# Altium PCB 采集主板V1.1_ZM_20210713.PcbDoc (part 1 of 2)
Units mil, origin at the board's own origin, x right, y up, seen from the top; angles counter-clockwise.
Board outline 5118.11 x 2559.06 mil, 4 copper layers (Top Layer, GND, Power, Bottom Layer), stack 30.635 mil thick; 191 components, 119 nets, 558 pads, 477 vias.
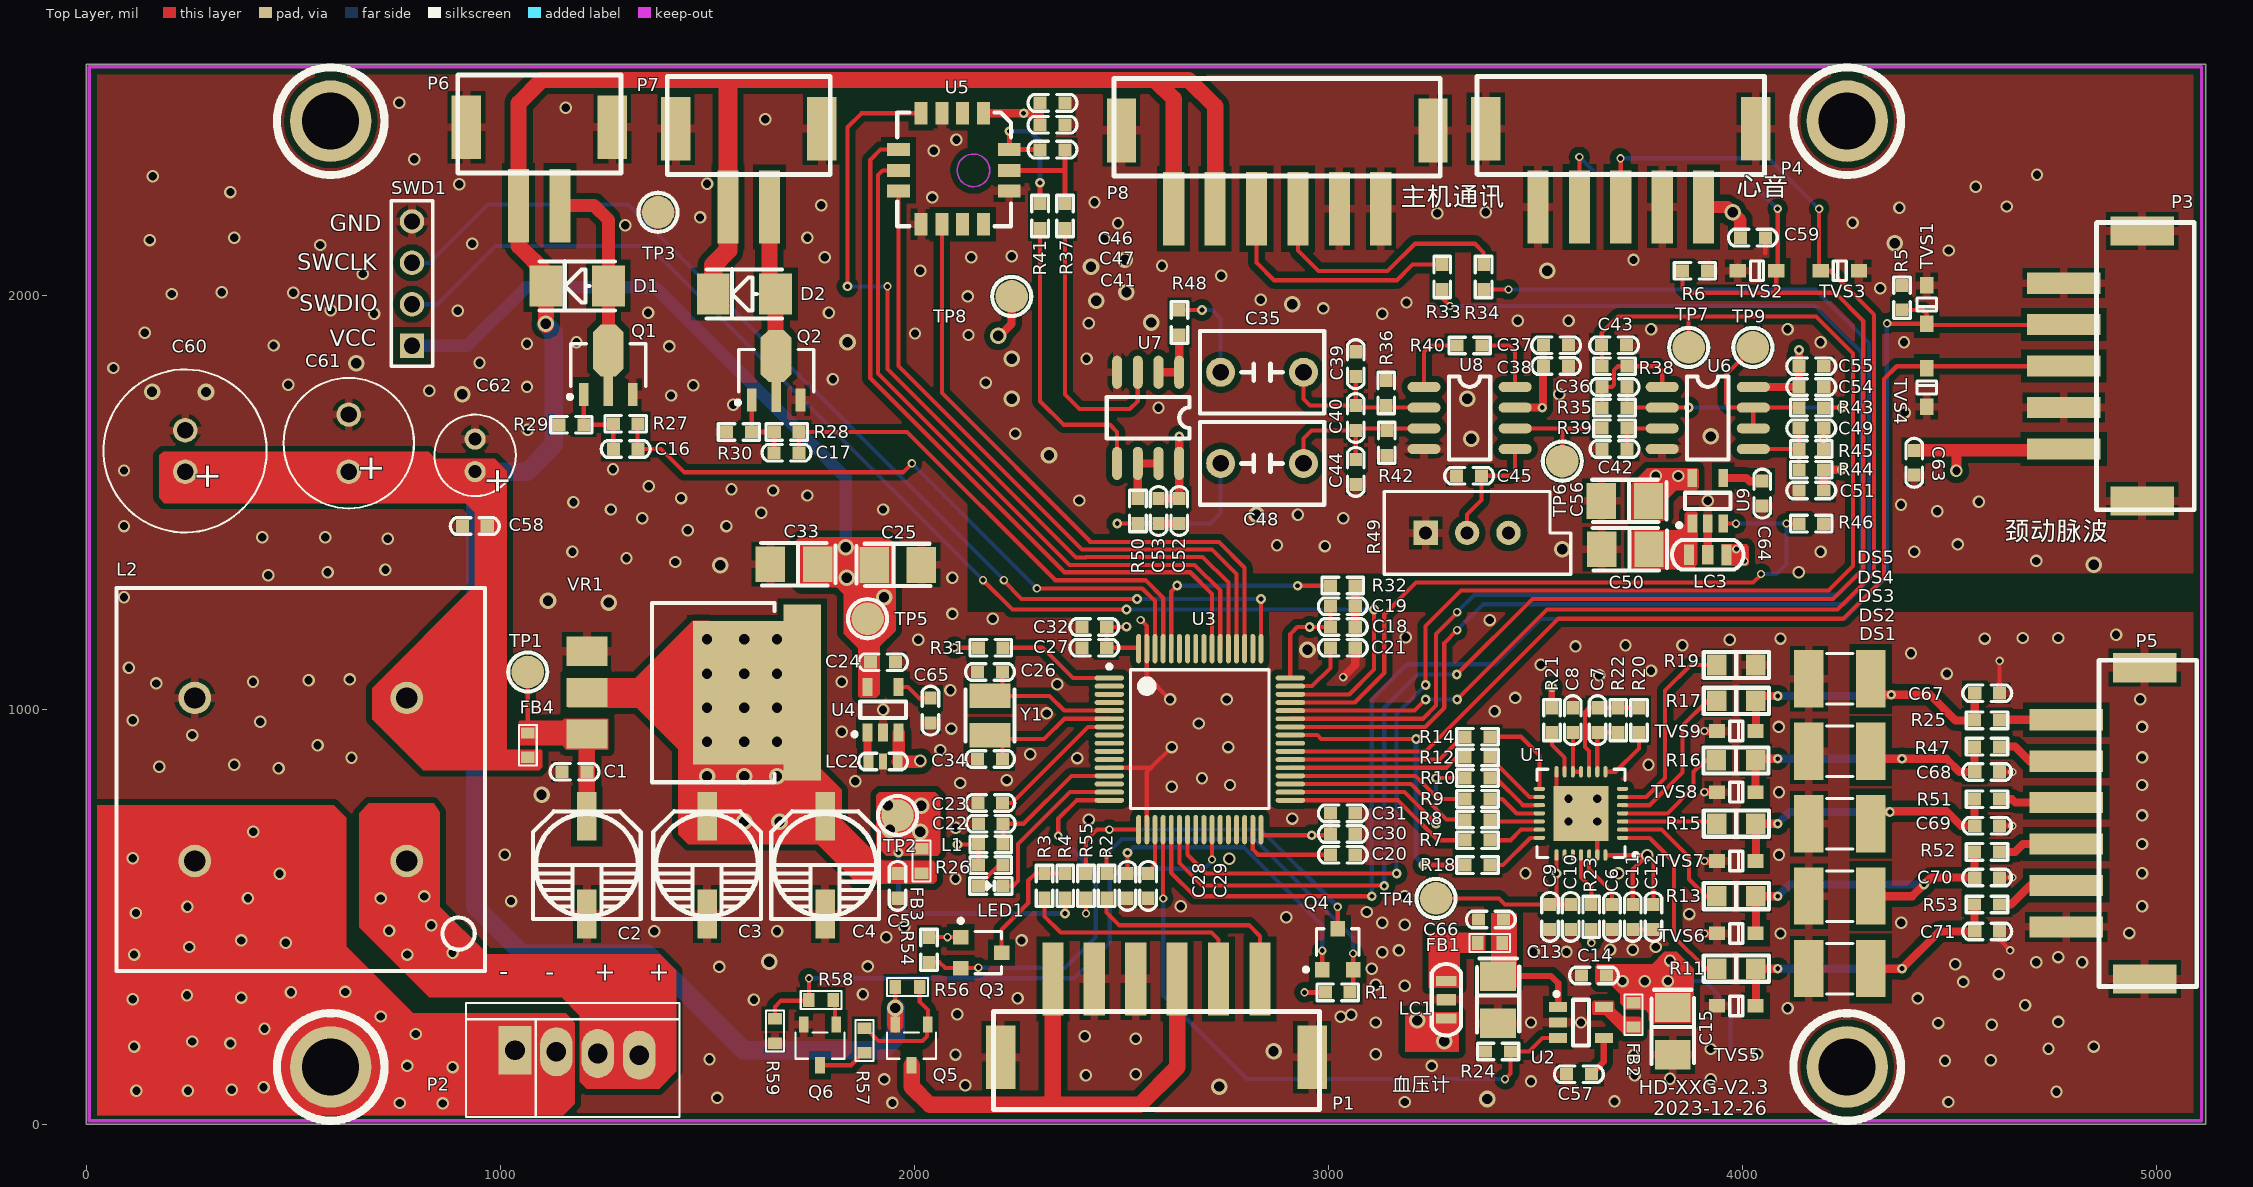
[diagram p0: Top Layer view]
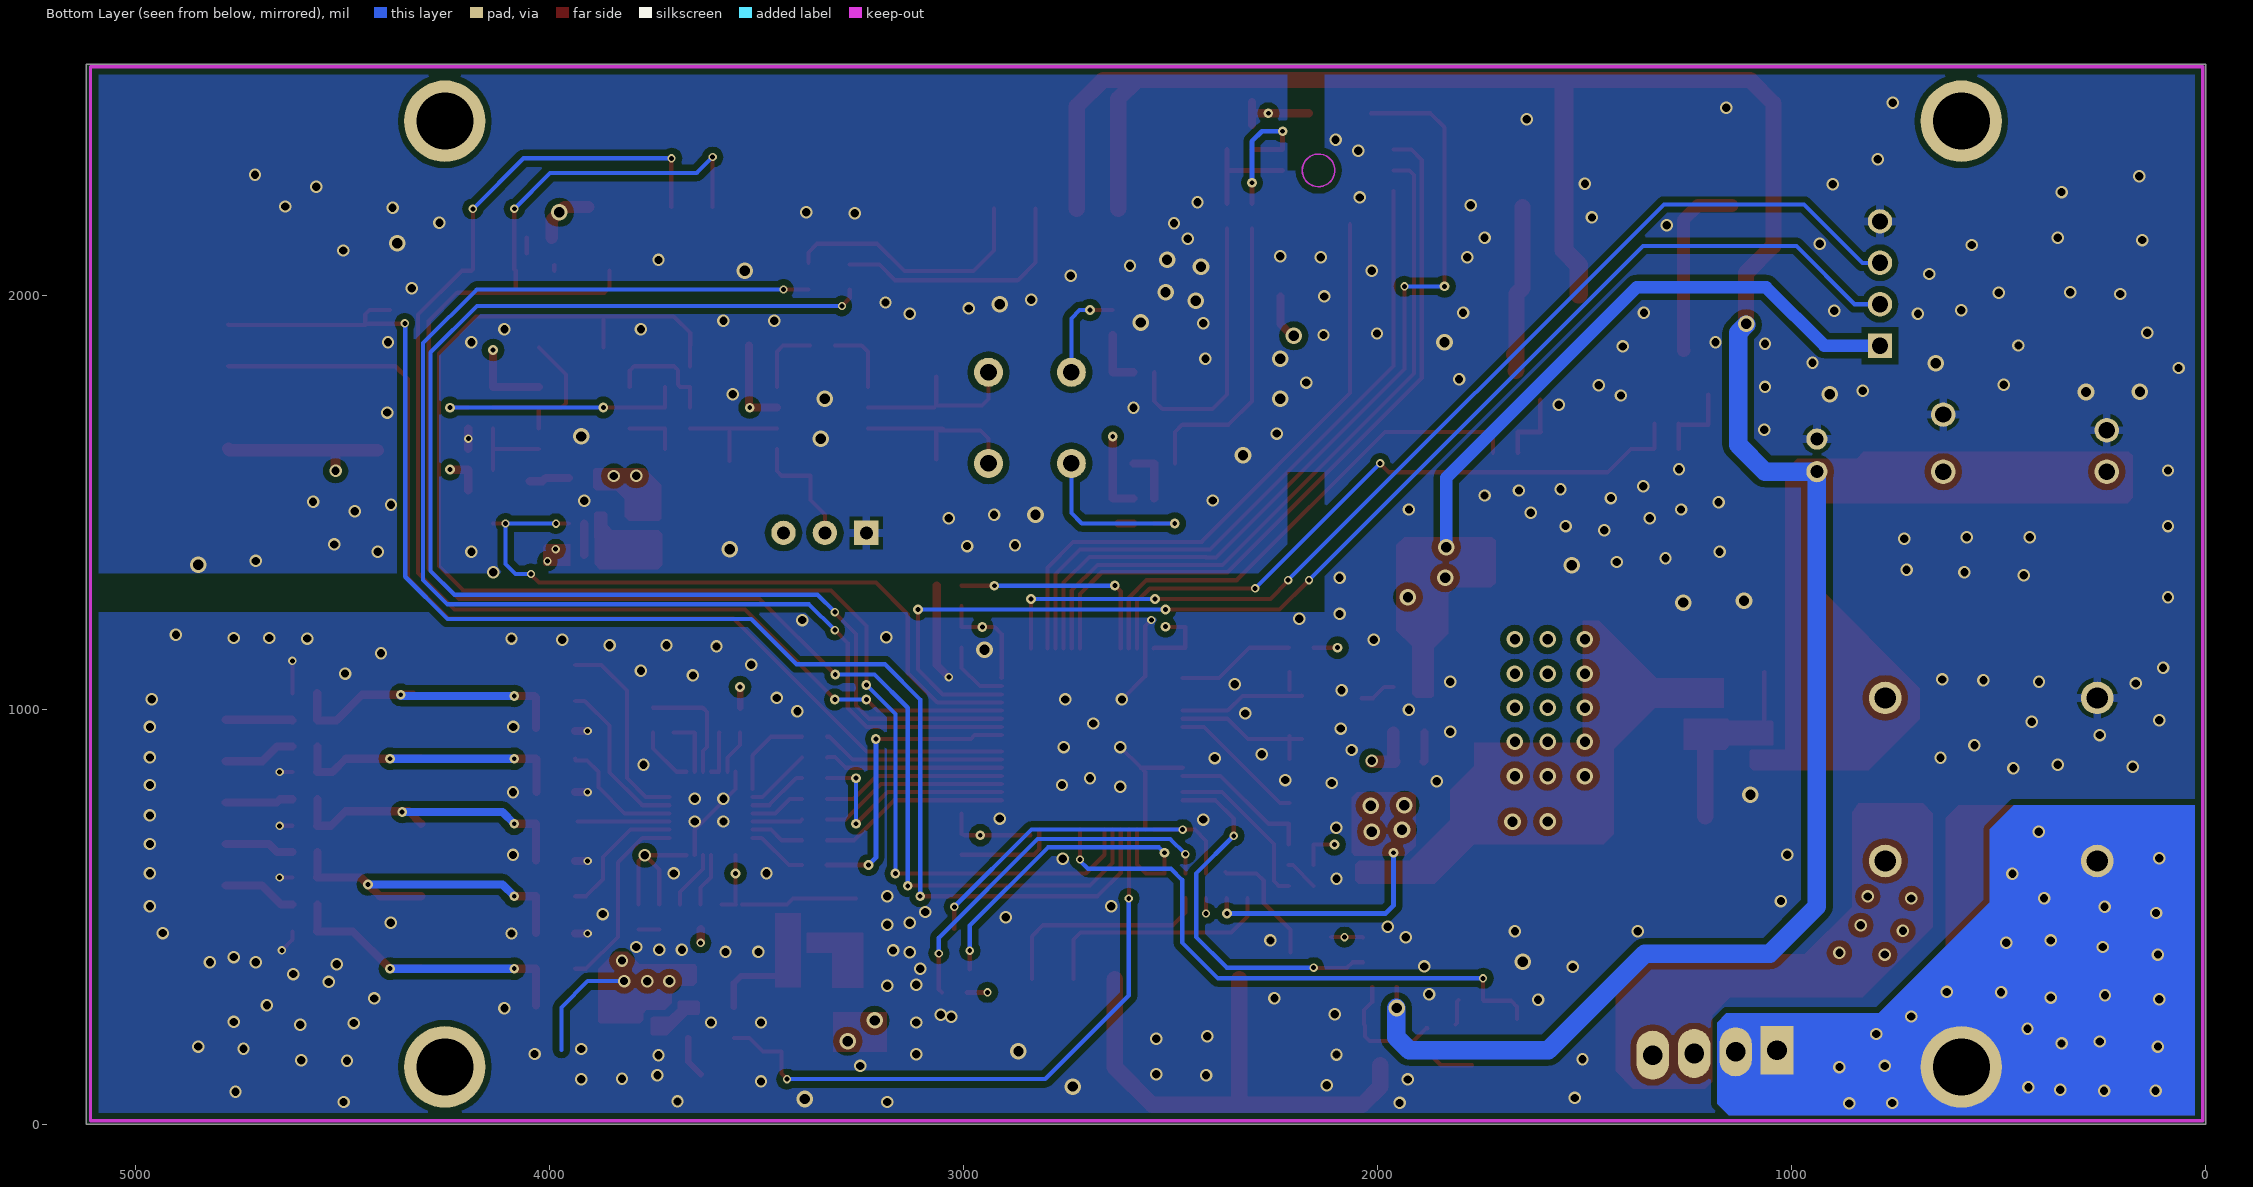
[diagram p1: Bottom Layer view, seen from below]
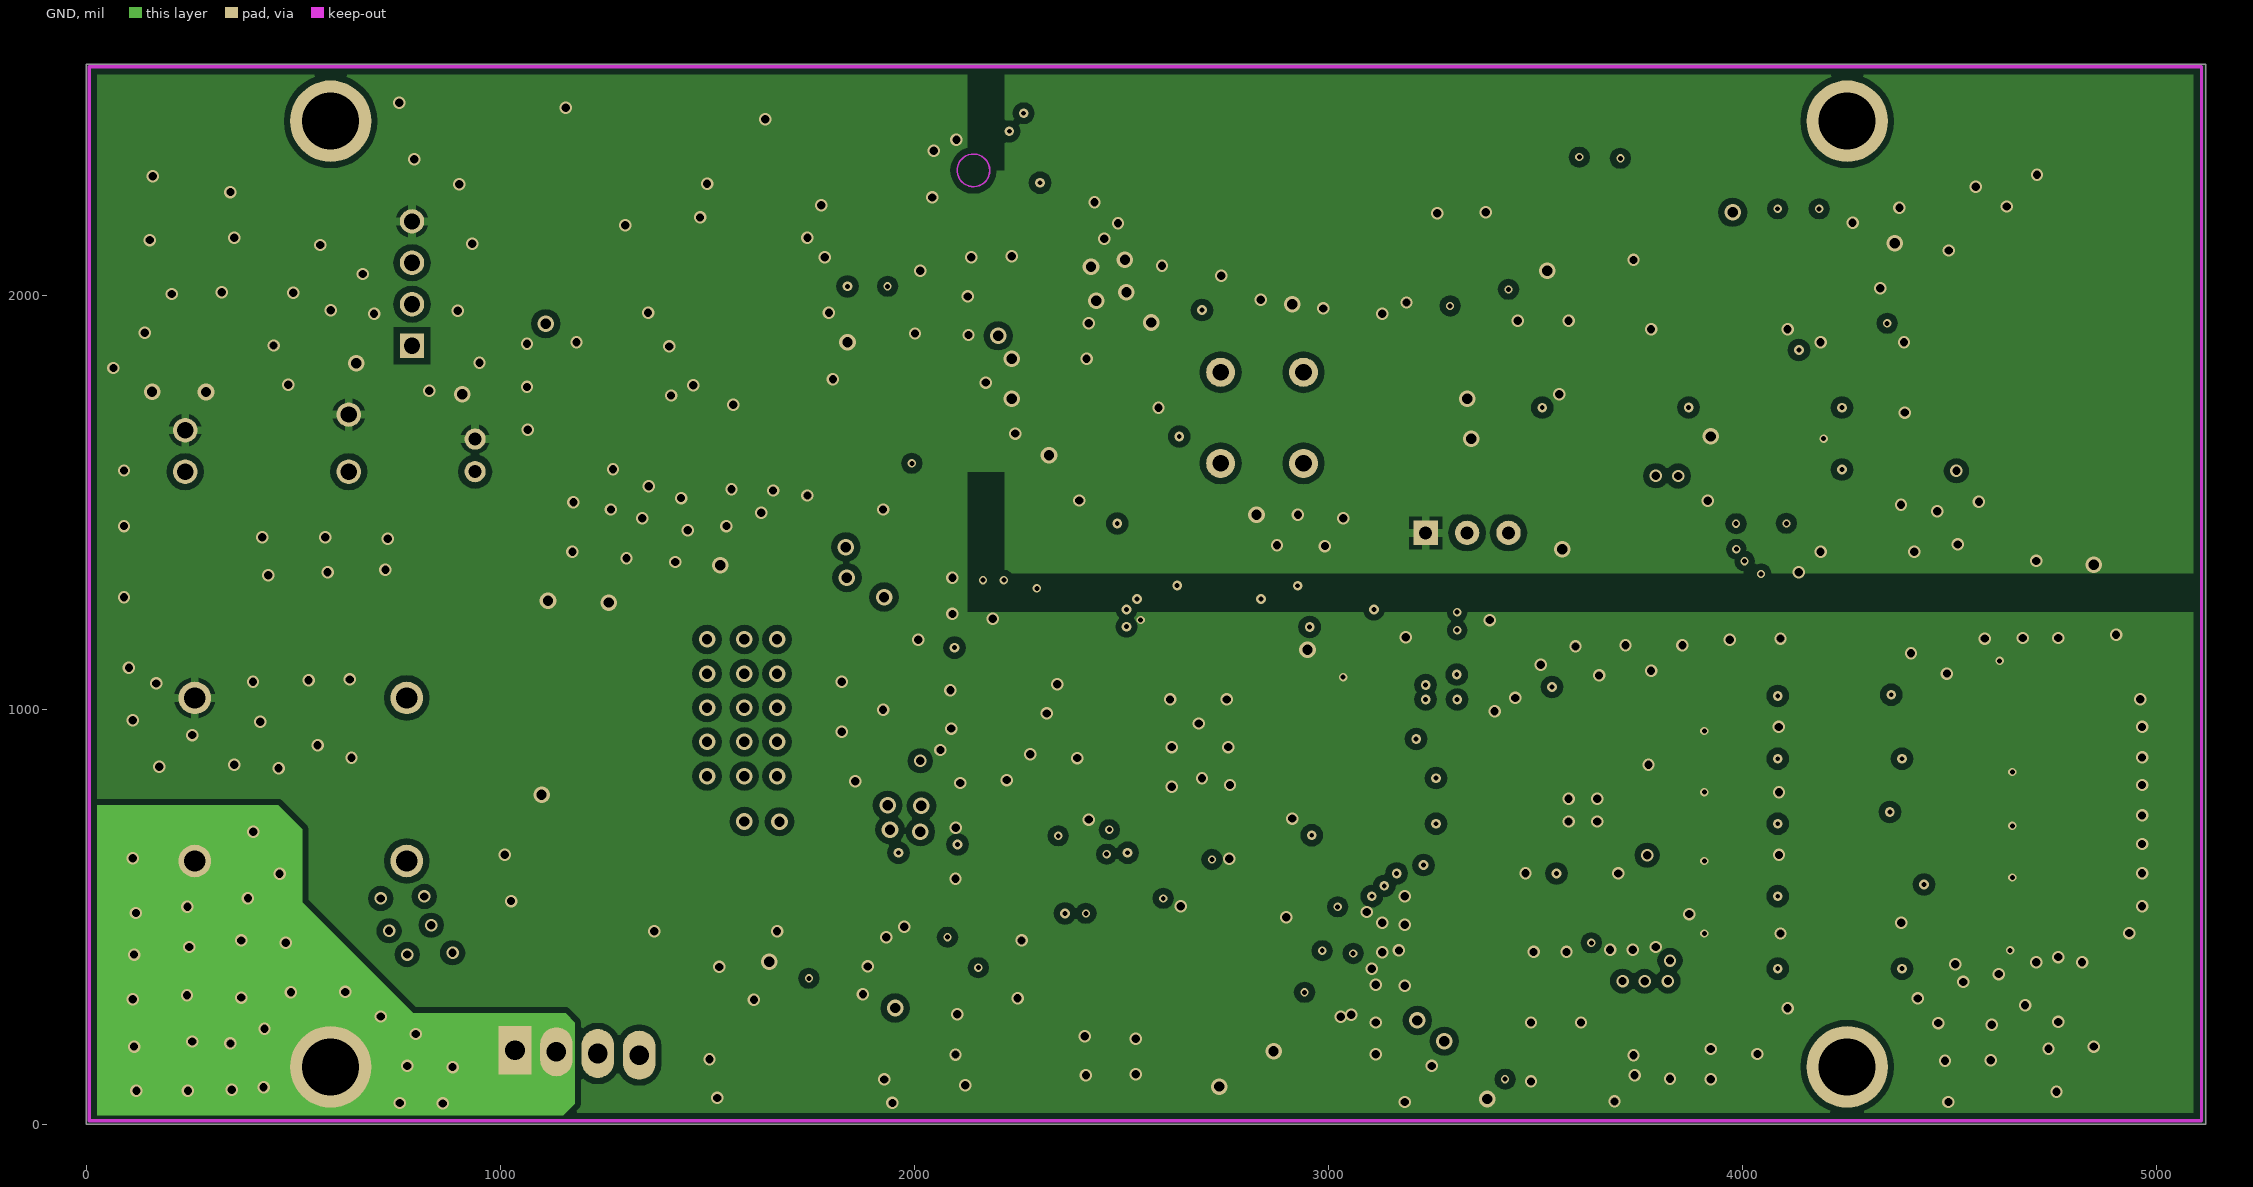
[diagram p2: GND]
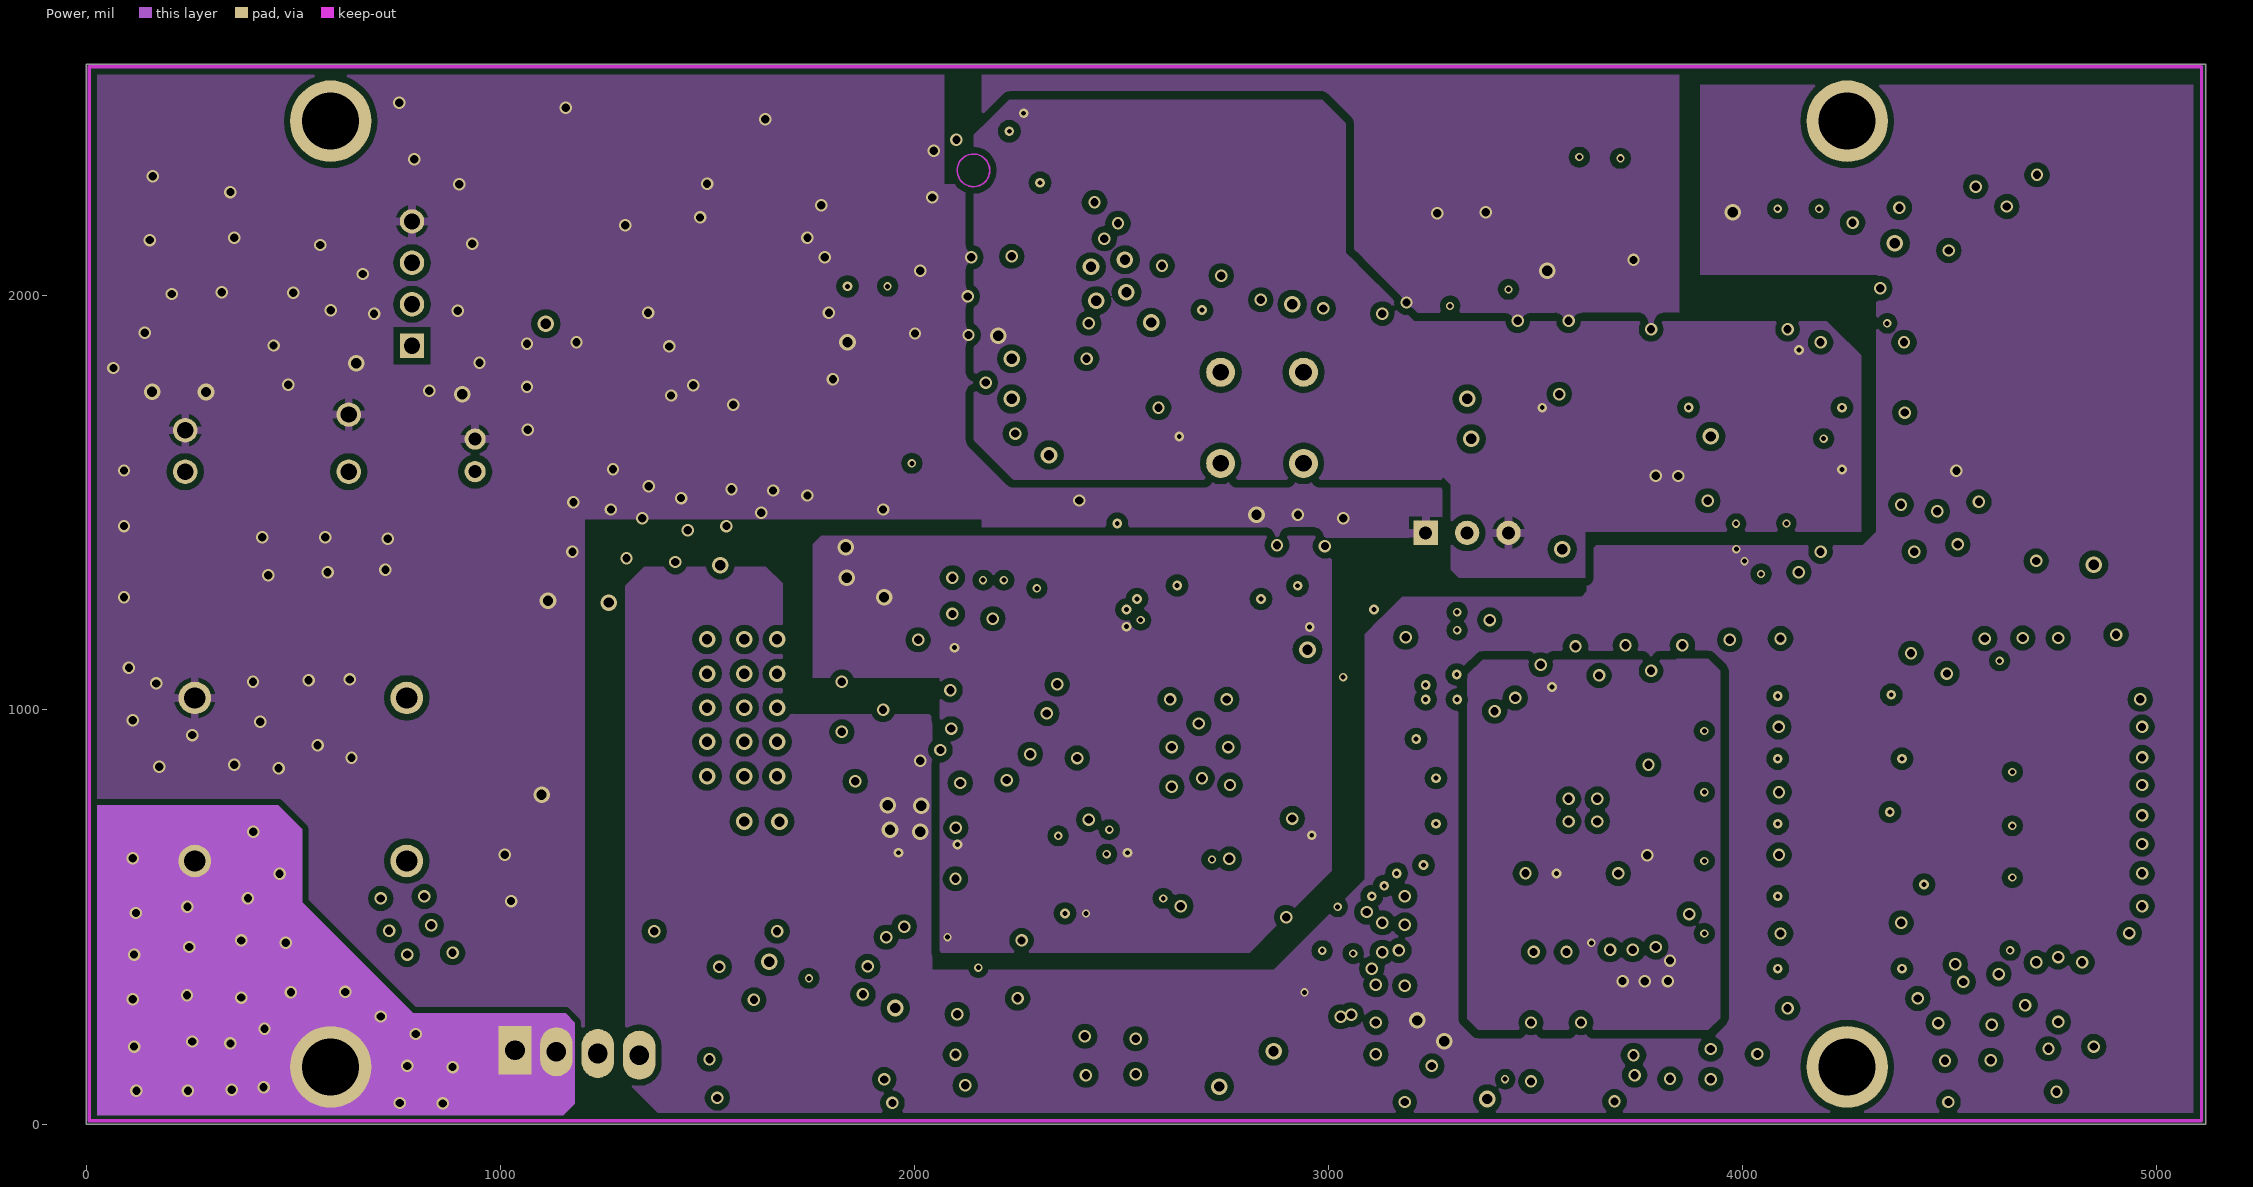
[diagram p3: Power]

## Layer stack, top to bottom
Top Solder: solder mask 0.4, Solder Resist, Dk 3.5
Top Layer: signal copper 1.4
Dielectric1: core 10, FR-4, Dk 4.2
GND: signal copper 1.4173
Dielectric3: prepreg 5, Dk 4.2
Power: signal copper 1.4173
Dielectric2: core 10, Dk 4.2
Bottom Layer: signal copper 1.4
Bottom Solder: solder mask 0.4, Solder Resist, Dk 3.5

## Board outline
0,0 5118.11,0 5118.11,2559.06 0,2559.06

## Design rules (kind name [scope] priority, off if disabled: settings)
Clearance ecg [InNetClass('ecg')] p1: gap=7.87 ignorepadtopadclearanceinfootprint=FALSE except(0: Arc-Hole Track-Hole SMDPad-Hole THPad-Hole Via-Hole Fill-Hole Poly-Hole Region-Hole Text-Hole; 50: Track-Poly SMDPad-Poly Via-Poly)
Clearance Clearance_1 [InNetClass('ecg')] p2: gap=15 ignorepadtopadclearanceinfootprint=FALSE except(0: Arc-Hole Track-Hole SMDPad-Hole THPad-Hole Via-Hole Fill-Hole Poly-Hole Region-Hole Text-Hole; 35: Poly-Poly; 40: Track-Poly)
Clearance [All] p3: gap=7.87 ignorepadtopadclearanceinfootprint=FALSE except(0: Arc-Hole Track-Hole SMDPad-Hole THPad-Hole Via-Hole Fill-Hole Poly-Hole Region-Hole Text-Hole; 15: Arc-Poly Track-Poly SMDPad-Poly THPad-Poly Via-Poly Fill-Poly Poly-Region; 20: Poly-Poly)
ComponentClearance [All] p1 off: gap=10 collisioncheckmode=3 verticalgap=10 showdistances=FALSE
FabricationTestpoint [(IsPad And (OnTopLayer Or OnBottomLayer))] p1: side=3 testpointundercomponent=TRUE minsize=40 maxsize=100 preferedsize=60 minholesize=0 maxholesize=40 preferedholesize=32 testpointgrid=1 allowsidetop=TRUE allowsidebottom=TRUE usegrid=TRUE gridtolerance=0.01
HoleSize [All] p1: absolutevalues=TRUE maxlimit=393.7 minlimit=1 maxpercent=80.000 minpercent=20.000
PolygonConnect PolygonConnect_1 [isvia] p1: connectstyle=Direct reliefconductorwidth=10 reliefentries=4 polygonreliefangle="90 Angle" airgapwidth=10
PolygonConnect [All] p2: connectstyle=Relief reliefconductorwidth=20 reliefentries=4 polygonreliefangle="90 Angle" airgapwidth=10
RoutingVias [All] p1: holewidth=11.81 width=23.62 viastyle="Through Hole" minholewidth=3.94 minwidth=11.81 maxholewidth=23.62 maxwidth=39.37
SolderMaskExpansion [All] p1: expansion=4 istentingtop=FALSE
Width [All] p1: maxlimit=78.74 minlimit=10 preferedwidth=10
27 further rules are at their usual default settings.

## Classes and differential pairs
component class 控制部分: C16 C17 C18 C19 C20 C21 C22 C23 C24 C25 C26 C27 C28 C29 C30 C31 C32 C33 C34 C65 D1 D2 L1 LC2 LED1 P6 P7 P8 Q1 Q2 R26 R27 R28 R29 R30 R31 R32 R33 R34 SWD1 TP5 U3 U4 Y1
component class PRESS: C35 C36 C37 C38 C39 C40 C41 C42 C43 C44 C45 C46 C47 C48 C49 C50 C51 C52 C53 C54 C55 C56 C64 LC3 R35 R36 R37 R38 R39 R40 R41 R42 R43 R44 R45 R46 R48 R49 R50 TP6 TP7 TP8 TP9 U5 U6 U7 U8 U9
component class POWER: C1 C2 C3 C4 C5 C58 C59 C60 C61 C62 C63 FB3 FB4 L2 P1 P2 P3 P4 Q3 Q4 Q5 Q6 R1 R2 R3 R4 R5 R6 R54 R55 R56 R57 R58 R59 TP1 TP2 TP3 TVS1 TVS2 TVS3 TVS4 VR1
component class ECG: C6 C7 C8 C9 C10 C11 C12 C13 C14 C15 C57 C66 C67 C68 C69 C70 C71 DS1 DS2 DS3 DS4 DS5 FB1 FB2 LC1 P5 R7 R8 R9 R10 R11 R12 R13 R14 R15 R16 R17 R18 R19 R20 R21 R22 R23 R24 R25 R47 R51 R52 R53 TP4 TVS5 TVS6 TVS7 TVS8 TVS9 U1 U2

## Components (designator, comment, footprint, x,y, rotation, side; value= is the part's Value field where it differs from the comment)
C1 "0.1uF/50V/X5R" SMD-0603C 1179.25,850.39 r0 top
C2 "220uF 25V" SMD-6.3*7.7 1209.25,625 r90 top
C3 "220uF/25V" SMD-6.3*7.7 1499.25,625 r90 top
C4 "220uF/25V" SMD-6.3*7.7 1784.25,625 r90 top
C5 "0.1uF/50V/X5R" SMD-0603C 1959.25,575 r90 top
C6 "1uF/50V/X5R" SMD-0603C 3684.25,500 r90 top
C7 "1nF 50V" SMD-0603C 3649.25,975 r90 top
C8 "0.1uF/50V/X5R" SMD-0603C 3589.25,975 r270 top
C9 "10uF 10V" SMD-0603C 3534.25,500 r90 top
C10 "0.1uF/50V/X5R" SMD-0603C 3584.25,500 r90 top
C11 "10uF 10V" SMD-0603C 3734.25,500 r90 top
C12 "0.1uF/50V/X5R" SMD-0603C 3784.25,500 r90 top
C13 "100uF 6.3V" SMD-3528-B 3409.25,300 r270 top
C14 "0.1uF/50V/X5R" SMD-0603C 3640.58,358.62 r0 top
C15 "100uF 6.3V" SMD-3528-B 3830.76,224.09 r270 top
C16 "1uF/50V/X5R" SMD-0603C 1302.87,1629.53 r0 top
C17 "1uF/50V/X5R" SMD-0603C 1691.11,1620.73 r0 top
C18 "1uF/50V/X5R" SMD-0603C 3034.25,1200 r180 top
C19 "0.1uF/50V/X5R" SMD-0603C 3034.25,1250 r180 top
C20 "0.1uF/50V/X5R" SMD-0603C 3034.25,650 r180 top
C21 "0.1uF/50V/X5R" SMD-0603C 3034.25,1150 r180 top
C22 "0.1uF/50V/X5R" SMD-0603C 2184.25,725 r0 top
C23 "0.1uF/50V/X5R" SMD-0603C 2183.07,775 r180 top
C24 "0.1uF/50V/X5R" SMD-0603C 1924.25,1115 r180 top
C25 "100uF 6.3V" SMD-3528-B 1959.69,1350 r0 top
C26 "12P 50V" SMD-0603C 2182.3,1091.29 r0 top
C27 "1uF/50V/X5R" SMD-0603C 2434.25,1150 r0 top
C28 "0.1uF/50V/X5R" SMD-0603C 2514.25,575 r90 top
C29 "1uF/50V/X5R" SMD-0603C 2564.25,575 r90 top
C30 "0.1uF/50V/X5R" SMD-0603C 3034.25,700 r180 top
C31 "1uF/50V/X5R" SMD-0603C 3034.25,750 r180 top
C32 "0.1uF/50V/X5R" SMD-0603C 2434.25,1200 r0 top
C33 "100uF 6.3V" SMD-3528-B 1709.25,1351.57 r180 top
C34 "12P 50V" SMD-0603C 2182.3,881.29 r0 top
C35 "0.22uF 63V" CAP-7.5*5.08 2839.25,1815 r0 top
C36 "10pF  50V" SMD-0603C 3690.35,1779.53 r180 top
C37 "10uF 10V" SMD-0603C 3549.25,1880 r180 top
C38 "0.1uF/50V/X5R" SMD-0603C 3549.25,1830 r180 top
C39 "100pF 50V" SMD-0603C 3065.35,1834.53 r90 top
C40 "0.01uF/50V/X5R" SMD-0603C 3065.35,1704.53 r270 top
C41 "0.01uF/50V/X5R" SMD-0603C 2333.37,2352.43 r0 top
C42 "NC" SMD-0603C 3690.35,1629.53 r0 top
C43 "NC" SMD-0603C 3689.25,1880 r0 top
C44 "100pF 50V" SMD-0603C 3065.35,1574.53 r90 top
C45 "0.1uF/50V/X5R" SMD-0603C 3339.25,1565 r0 top
C46 "0.1uF/50V/X5R" SMD-0603C 2333.37,2465.39 r180 top
C47 "10uF 10V" SMD-0603C 2333.37,2412.43 r180 top
C48 "0.22uF 63V" CAP-7.5*5.08 2839.25,1595 r180 top
C49 "0.1uF/50V/X5R" SMD-0603C 4165.35,1679.53 r180 top
C50 "100uF 6.3V" SMD-3528-B 3716.54,1387.8 r180 top
C51 "0.1uF/50V/X5R" SMD-0603C 4165.35,1529.53 r0 top
C52 "10uF 10V" SMD-0603C 2639.25,1480 r90 top
C53 "0.1uF/50V/X5R" SMD-0603C 2589.25,1480 r90 top
C54 "10uF 10V" SMD-0603C 4165.35,1779.53 r180 top
C55 "0.1uF/50V/X5R" SMD-0603C 4165.35,1829.53 r180 top
C56 "100uF 6.3V" SMD-3528-B 3715.35,1504.53 r180 top
C57 "0.01uF/50V/X5R" SMD-0603C 3604.25,120 r0 top
C58 "0.1uF/50V/X5R" SMD-0603C 938.54,1443.57 r0 top
C59 "0.1uF/50V/X5R" SMD-0603C 4024.25,2140.07 r180 top
C60 "1000uF/25V" 10*16 239.25,1625 r270 top
C61 "470uF/25V" 8*12 634.25,1643.9 r270 top
C62 "33uF/25V" 5*7 939.25,1614.37 r270 top
C63 "0.1uF/50V/X5R" SMD-0603C 4413.71,1596.41 r90 top
C64 "NC" SMD-0603C 4047.04,1522.03 r90 top
C65 "NC" SMD-0603C 2038.69,998.03 r90 top
C66 "0.1uF/50V/X5R" SMD-0603C 3391.79,493.68 r180 top
C67 "22nF/50V/X5R" SMD-0603C 4590,1040 r180 top
C68 "22nF/50V/X5R" SMD-0603C 4590,850 r180 top
C69 "22nF/50V/X5R" SMD-0603C 4590,720 r180 top
C70 "22nF/50V/X5R" SMD-0603C 4590,595 r180 top
C71 "22nF/50V/X5R" SMD-0603C 4590,465 r180 top
D1 "1N4007" DO-214-AC 1185.8,2023.52 r180 top
D2 "1N4007" DO-214-AC 1589.25,2003.94 r180 top
DS1 "UN1812-90CSMD" SMD-1812 4234.25,375 r180 top
DS2 "UN1812-90CSMD" SMD-1812 4234.25,550 r180 top
DS3 "UN1812-90CSMD" SMD-1812 4234.25,725 r180 top
DS4 "UN1812-90CSMD" SMD-1812 4234.25,900 r180 top
DS5 "UN1812-90CSMD" SMD-1812 4234.25,1075 r180 top
FB1 "30R/5A" 0603r 3359.65,436.8 r0 top value=10mH
FB2 "30R/5A" 0603r 3736.07,234.11 r90 top value=10mH
FB3 "30R/5A" 0603r 2016.77,605.23 r90 top value=10mH
FB4 "30R/5A" 0603r 1066.4,885 r90 top value=10mH
L1 "MPZ1608D101BTA00" SMD-0603 2184.25,675 r180 top
L2 "LCM" LCM 774.25,635 r180 top
LC1 "NFM18PC104R1C3" NFM21P-0805 3284.25,300 r270 top
LC2 "NFM18PC104R1C3" NFM18P-0603 1924.25,875 r0 top
LC3 "NFM18PC104R1C3" NFM21P-0805 3915.35,1374.53 r0 top
LED1 "蓝" SMD-0603D 2184.25,575 r0 top
P1 "XH2.54 6P 立贴" XH-2.54-6P-LI 2584.25,350 r180 top
P2 "XH2.54-4P直插" 4X2.54MMZ 1035.61,178.12 r0 top
P3 "XH2.54 6P 立贴" XH-2.54-5P-LI 4775,1830 r270 top
P4 "XH2.54 5P 立贴" XH-2.54-5P-LI 3705.35,2214 r0 top
P5 "XH2.54 6P 立贴" XH-2.54-6P-LI 4781.02,725.98 r270 top
P6 "VH2.54-2P" XH-2.54-2P-LI 1094.24,2217.35 r0 top
P7 "VH2.54-2P" XH-2.54-2P-LI 1599.97,2214 r0 top
P8 "XH2.54 6P 立贴" XH-2.54-6P-LI 2875.88,2209.74 r0 top
Q1 "D882M" SOT-89-3 1260.7,1832.34 r0 top
Q2 "D882M" SOT-89-3 1666.11,1818.61 r0 top
Q3 "AO3400" SOT-23 2161.02,413.78 r270 top
Q4 "AO3400" SOT-23 3021.96,421.91 r0 top
Q5 "SI2347" SOT23-3 2032.38,240.29 r90 top
Q6 "S8050" SOT23-3 1811.46,240.25 r90 top
R1 "10K" SMD-0603 3021.96,317.76 r0 top
R2 "20R" SMD-0603 2464.06,575 r90 top
R3 "20R" SMD-0603 2314.06,575 r90 top
R4 "10K" SMD-0603 2364.06,575 r270 top
R5 "10K" SMD-0603 4384.25,1995 r270 top
R6 "10K" SMD-0603 3884.25,2060 r180 top
R7 "33R" SMD-0603 3359.25,685 r0 top
R8 "33R" SMD-0603 3359.25,735 r0 top
R9 "33R" SMD-0603 3359.25,785 r0 top
R10 "33R" SMD-0603 3359.25,835 r0 top
R11 "0R" SMD-0805 3984.25,375 r180 top
R12 "33R" SMD-0603 3359.25,885 r0 top
R13 "0R" SMD-0805 3984.25,550 r180 top
R14 "33R" SMD-0603 3359.25,935 r0 top
R15 "0R" SMD-0805 3984.25,725 r180 top
R16 "0R" SMD-0805 3983.46,877.95 r180 top
R17 "0R" SMD-0805 3984.25,1021.65 r180 top
R18 "33R" SMD-0603 3359.25,625 r0 top
R19 "0R" SMD-0805 3984.25,1108.27 r180 top
R20 "10K" SMD-0603 3749.25,975 r90 top
R21 "1M" SMD-0603 3539.25,975 r270 top
R22 "10M" SMD-0603 3699.25,975 r90 top
R23 "1M" SMD-0603 3634.25,500 r90 top
R24 "10K" SMD-0603 3409.25,175 r180 top
R25 "15K" SMD-0603 4589.55,974.56 r180 top
R26 "4.7K" SMD-0603 2184.25,625 r0 top
R27 "100R" SMD-0603 1302.87,1690.68 r0 top
R28 "100R" SMD-0603 1691.5,1670.73 r0 top
R29 "10K" SMD-0603 1171.65,1688.43 r180 top
R30 "10K" SMD-0603 1576.11,1670.73 r180 top
R31 "100K" SMD-0603 2184.25,1150 r0 top
R32 "10K" SMD-0603 3034.25,1300 r0 top
R33 "10R" SMD-0603 3274.25,2045 r270 top
R34 "10R" SMD-0603 3374.25,2045 r270 top
R35 "100K" SMD-0603 3690.35,1729.53 r180 top
R36 "4.7M" SMD-0603 3139.25,1765 r90 top
R37 "10K" SMD-0603 2363.37,2192.43 r90 top
R38 "1K" SMD-0603 3690.35,1829.53 r180 top
R39 "10K" SMD-0603 3690.35,1679.53 r0 top
R40 "1K" SMD-0603 3340.35,1879.53 r0 top
R41 "10K" SMD-0603 2303.37,2192.43 r90 top
R42 "4.7M" SMD-0603 3140.35,1644.53 r90 top
R43 "3.3K" SMD-0603 4165.35,1729.53 r0 top
R44 "10K" SMD-0603 4165.35,1579.53 r180 top
R45 "10K" SMD-0603 4165.35,1629.53 r180 top
R46 "10K" SMD-0603 4165.35,1449.53 r0 top
R47 "15K" SMD-0603 4589.55,911.05 r180 top
R48 "10K" SMD-0603 2639.76,1935 r270 top
R49 "20K" VR-05 3334.25,1427.17 r0 top
R50 "10K" SMD-0603 2539.37,1480 r90 top
R51 "15K" SMD-0603 4589.55,784.03 r180 top
R52 "15K" SMD-0603 4589.55,657.02 r180 top
R53 "15K" SMD-0603 4589.55,530.01 r180 top
R54 "10K" SMD-0603 2035.21,420.39 r90 top
R55 "10K" SMD-0603 2414.06,575 r90 top
R56 "100K" 0603R 2012.95,331.12 r180 top
R57 "1K" 0603R 1879.82,171.97 r90 top
R58 "1K" 0603R 1804.25,299.01 r180 top
R59 "10K" 0603R 1663.14,253.94 r270 top
SWD1 "SIP-4" SIP-4 786.92,2029.19 r90 top
TP1 "TP" TP 1066.4,1091.29 r0 top
TP2 "TP" TP 1959.25,745 r0 top
TP3 "TP" TP 1380.95,2201.09 r0 top
TP4 "TP" TP 3259.25,544.68 r0 top
TP5 "TP" TP 1886.85,1220 r270 top
TP6 "TP" TP 3564.25,1600.39 r0 top
TP7 "TP" TP 3869.25,1875 r0 top
TP8 "TP" TP 2234.72,1998.13 r0 top
TP9 "TP" TP 4024.25,1875 r90 top
TVS1 "TVS-S" SOD-323 4444.25,1978.54 r270 top
TVS2 "TVS-S" SOD-323 4034.25,2060 r0 top
TVS3 "TVS-S" SOD-323 4234.25,2060 r180 top
TVS4 "TVS-S" SOD-323 4444.25,1778.07 r90 top
TVS5 "TVS-S" SOD-323 3984.25,285 r0 top
TVS6 "TVS-S" SOD-323 3984.25,460 r0 top
TVS7 "TVS-S" SOD-323 3984.25,635 r0 top
TVS8 "TVS-S" SOD-323 3984.25,801.18 r0 top
TVS9 "TVS-S" SOD-323 3984.25,948.82 r0 top
U1 "ADS1293CISQ/NOPB" QFN-28 3609.25,750 r0 top
U2 "TPS73633DBVR" SOT23-5 3609.25,245 r0 top
U3 "STM32F405RGT6" LQFP64_N 2688.98,929.13 r0 top
U4 "LP5907MFX-3.3" SOT23-5 1924.25,1000 r90 top
U5 "MMR901XA" MMR901XA 2083.37,2302.43 r180 top
U6 "OPA2376AID" SOIC-8 3915.35,1704.53 r0 top
U7 "OPA2376AID" SOIC-8 2564.25,1705 r270 top
U8 "AD623AR" SOIC-8 3340.35,1704.53 r0 top
U9 "LP5907MFX-3.3" SOT23-5 3915.35,1504.53 r90 top
VR1 "LM1085S-5.0V" TO-263-3 1209.25,1041.78 r270 top
Y1 "8MHz" XTAL-3225-2 2182.3,986.29 r90 top

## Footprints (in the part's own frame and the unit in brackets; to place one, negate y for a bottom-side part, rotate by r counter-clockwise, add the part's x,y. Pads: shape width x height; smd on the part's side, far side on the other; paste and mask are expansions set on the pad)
4X2.54MMZ [mm] "接插件2.54-3P"
  rect 2x3 hole 1.2: 1(0,0)
  oval 2x3 hole 1.2: 2(2.54,-0.1) 3(5.08,-0.2) 4(7.62,-0.3)
  silkscreen extent -3,-4.1 10.08,2.9
5*7 [mm]
  round 1.3 hole 0.8: 1(1,0) 2(-1,0)
  silkscreen extent -2.5,-2.5 2.5,2.5
8*12 [mm]
  round 1.5 hole 1: 1(1.75,0) 2(-1.75,0)
  silkscreen extent -4,-4 4,4
10*16 [mm]
  round 1.5 hole 1: 1(1.27,0) 2(-1.27,0)
  silkscreen extent -5,-5 5,5
0603r [mm]
  rect 0.7x0.85 smd: 1(0,0) 2(1.5,0)
  silkscreen extent -0.5,-0.55 2,0.55
0603R [mm]
  rect 0.7x0.85 smd: 1(0,0) 2(1.5,0)
  silkscreen extent -0.5,-0.55 2,0.55
CAP-7.5*5.08 [mil]
  round 70 hole 40: 1(-100,0) 2(100,0)
  silkscreen extent -150,-100 150,100
DO-214-AC [mm] "Molded Diode, 2-Leads, Body 4.5x2.6mm, IPC Medium Density"
  rect 2x2.5 smd: 1(-1.915,0) 2(1.915,0)
  silkscreen extent -2.3,-1.52 2.3,1.5, body extent -2.3,-1.35 2.3,1.35, height 2.4
LCM [mm]
  round 2 hole 1.3: 1(0,0) 2(0,-10) 3(13,-10) 4(13,0)
  silkscreen extent -4.8,-16.75 17.8,6.75
LQFP64_N [mm] "Thin QFP, 64-Leads, Body 10x10mm, Pitch 0.5mm, IPC Medium Density"
  oval 1.8x0.3 smd: 1(-5.55,3.75) 2(-5.55,3.25) 3(-5.55,2.75) 4(-5.55,2.25) 5(-5.55,1.75) 6(-5.55,1.25) 7(-5.55,0.75) 8(-5.55,0.25) 9(-5.55,-0.25) 10(-5.55,-0.75) 11(-5.55,-1.25) 12(-5.55,-1.75) 13(-5.55,-2.25) 14(-5.55,-2.75) 15(-5.55,-3.25) 16(-5.55,-3.75) 33(5.55,-3.75) 34(5.55,-3.25) 35(5.55,-2.75) 36(5.55,-2.25) 37(5.55,-1.75) 38(5.55,-1.25) 39(5.55,-0.75) 40(5.55,-0.25) 41(5.55,0.25) 42(5.55,0.75) 43(5.55,1.25) 44(5.55,1.75) 45(5.55,2.25) 46(5.55,2.75) 47(5.55,3.25) 48(5.55,3.75)
  oval 0.3x1.8 smd: 17(-3.75,-5.55) 18(-3.25,-5.55) 19(-2.75,-5.55) 20(-2.25,-5.55) 21(-1.75,-5.55) 22(-1.25,-5.55) 23(-0.75,-5.55) 24(-0.25,-5.55) 25(0.25,-5.55) 26(0.75,-5.55) 27(1.25,-5.55) 28(1.75,-5.55) 29(2.25,-5.55) 30(2.75,-5.55) 31(3.25,-5.55) 32(3.75,-5.55) 49(3.75,5.55) 50(3.25,5.55) 51(2.75,5.55) 52(2.25,5.55) 53(1.75,5.55) 54(1.25,5.55) 55(0.75,5.55) 56(0.25,5.55) 57(-0.25,5.55) 58(-0.75,5.55) 59(-1.25,5.55) 60(-1.75,5.55) 61(-2.25,5.55) 62(-2.75,5.55) 63(-3.25,5.55) 64(-3.75,5.55)
  silkscreen extent -5.67,-4.25 4.25,4.57, body extent -5,-5 5,5, height 1.6
MMR901XA [mm] "传感器"
  rect 0.8x1.4 smd: 1(-2.105,-3.5) 2(-0.835,-3.5) 3(0.435,-3.5) 4(1.705,-3.5) 8(1.705,3.3) 9(0.435,3.3) 10(-0.835,3.3) 11(-2.105,3.3)
  rect 1.4x0.8 smd: 5(3.1,-1.27) 6(3.1,0) 7(3.1,1.27) 12(-3.7,1.27) 13(-3.7,0) 14(-3.7,-1.27)
  Keep-Out Layer circle w0.1: c-1.5,0 r1
  silkscreen extent -3.81,-3.56 3.18,3.43
NFM18P-0603 [mm] "三端滤波电容"
  rect 0.6x0.8 smd: 1(-0.9,0) 3(0.9,0)
  rect 0.5x1 smd: 2(0,0)
  silkscreen extent -1.5,-0.51 1.5,0.51
NFM21P-0805 [mm] "三端滤波电容"
  rect 0.6x1.27 smd: 1(-1.143,0) 3(1.143,0)
  rect 0.7x1.2 smd: 2(0,0)
  silkscreen extent -2.2,-0.9 2.2,0.9, body extent -1,-0.62 1,0.63, height 0.85
QFN-28 [mm]
  rect 3.38x3.38 smd: 0(0,0)
  oval 0.7x0.25 smd: 1(2.55,-1.5) 2(2.55,-1) 3(2.55,-0.5) 4(2.55,0) 5(2.55,0.5) 6(2.55,1) 7(2.55,1.5) 15(-2.55,1.5) 16(-2.55,1) 17(-2.55,0.5) 18(-2.55,0) 19(-2.55,-0.5) 20(-2.55,-1) 21(-2.55,-1.5)
  oval 0.25x0.7 smd: 8(1.5,2.55) 9(1,2.55) 10(0.5,2.55) 11(0,2.55) 12(-0.5,2.55) 13(-1,2.55) 14(-1.5,2.55) 22(-1.5,-2.55) 23(-1,-2.55) 24(-0.5,-2.55) 25(0,-2.55) 26(0.5,-2.55) 27(1,-2.55) 28(1.5,-2.55)
  silkscreen extent -2.7,-2.7 3.48,2.7, body extent -2.55,-2.55 2.55,2.55, height 1
SIP-4 [mm]
  rect 1.5x1.5 hole 1: 1(-3.81,0)
  round 1.5 hole 1: 2(-1.27,0) 3(1.27,0) 4(3.81,0)
  silkscreen extent -5.08,-1.27 5.08,1.27
SMD-6.3*7.7 [mm] "35V 100uF"
  rect 3x1.2 smd: 1(3,0) 2(-3,0)
  silkscreen extent -3.3,-3.3 3.3,3.3, body extent -3.37,-3.42 3.13,3.08, height 9.7
SMD-0603 [mil] "W1/32贴片电阻"
  rect 31.5x30 smd: 1(-30,0) 2(30,0)
  silkscreen extent -50,-20 50,20, body extent -31,-16 32,16, height 18
SMD-0603C [mil] "贴片电容"
  rect 31.5x30 smd: 1(-30,0) 2(30,0)
  silkscreen extent -59,-20 59,20, body extent -31,-16 32,16
SMD-0603D [mil] "贴片二极管"
  rect 31.5x30 smd: 1(-30,0) 2(30,0)
  silkscreen extent -51,-20 51,20, body extent -31,-16 32,16, height 26
SMD-0805 [mm] "贴片电阻"
  rect 1.2x1.27 smd: 1(-1.2,0) 2(1.2,0)
  silkscreen extent -2,-0.8 2,0.8, body extent -1,-0.63 1,0.63, height 0.55
SMD-1812 [mm] "贴片电阻"
  rect 1.8x3.5 smd: 1(-1.9,0) 2(1.9,0)
  silkscreen extent -0.8,-1.55 0.8,1.55, body extent -2.4,-1.7 2.4,1.7, height 1.4
SMD-3528-B [mm] "Molded Capacitor, 2-Leads, Body 3.5x2.2mm, IPC Medium Density"
  rect 1.8x2.2 smd: 1(-1.45,0) 2(1.45,0)
  silkscreen extent -2.54,-1.3 2.01,1.3, body extent -1.85,-1.46 1.85,1.47, height 2.03
SOD-323 [mm] "贴片二极管"
  rect 1x0.83 smd: 1(-1.18,0) 2(1.18,0)
  silkscreen extent -0.4,-0.6 0.4,0.6, body extent -1.4,-0.68 1.4,0.67, height 0.75
SOIC-8 [mil] "中体积贴片"
  oval 80x24 smd: 1(-110,75) 2(-110,25) 3(-110,-25) 4(-110,-75) 5(110,-75) 6(110,-25) 7(110,25) 8(110,75)
  silkscreen extent -50,-100 50,100, body extent -119,-99 119,99, height 63
SOT23-3 [mm]
  rect 1x0.6 smd: 1(0,0) 2(0,2) 3(-2.5,1)
  silkscreen extent -2.1,-0.5 -0.5,2.5
SOT23-5 [mm] "SOT23, 5-Leads, Body 3.1x2.6mm (max), Pitch 0.95mm, IPC Medium Density"
  rect 1.1x0.6 smd: 1(-1.4,0.95) 2(-1.4,0) 3(-1.4,-0.95) 4(1.4,-0.95) 5(1.4,0.95)
  silkscreen extent -1.62,-1.4 0.5,1.87, body extent -1.25,-1.5 1.25,1.5, height 1.1
SOT-23 [mm] "SOT-23; 3 Leads; Body 3.0 x 2.6 mm, inc. leads (LxW max)"
  rect 0.9x0.95 smd: 1(-0.95,-1.25) 2(0.95,-1.25) 3(0,1.25)
  silkscreen extent -2.07,-1.37 1.3,1.25
SOT-89-3 [mm] "三极管或MOS"
  rect 0.6x1.4 smd: 1(-1.5,-1.8) 3(1.5,-1.8)
  rect 0.6x2 smd: 2(0,-1.524)
  oct 1.9x3.2 smd: 2(0,0.9)
  silkscreen extent -2.47,-2.07 2.3,1.3, body extent -2.25,-2.1 2.25,2.2, height 1.51
TO-263-3 [mm]
  rect 1.8x2.5 smd: 1(-2.54,0) 2(0,0) 3(2.54,0)
  rect 10.8x2.3 smd: 2(0,13.208)
  rect 8.8x6 smd: 2(0,9.5)
  silkscreen extent -5.5,4 5.5,11.5
TP [mm] "Test Point"
  round 2 smd: 1(0,0)
  silkscreen extent -1.2,-1.2 1.2,1.2
VR-05 [mm] "立式精密变阻器"
  rect 1.5x1.5 hole 0.8: 1(-2.54,0)
  round 1.5 hole 0.8: 2(0,0) 3(2.54,0)
  silkscreen extent -5.08,-2.54 6.35,2.54
XH-2.54-2P-LI [mm] "接插件2.54-2P"
  rect 1.8x3.9 smd: 0(-4.47,4.8) 0(4.47,4.8)
  rect 1.3x4.5 smd: 1(-1.27,0) 2(1.27,0)
  silkscreen extent -5,2 5,8
XH-2.54-5P-LI [mm] "接插件2.54-3P"
  rect 1.8x3.9 smd: 0(-8.28,4.8) 0(8.28,4.8)
  rect 1.3x4.5 smd: 1(-5.08,0) 2(-2.54,0) 3(0,0) 4(2.54,0) 5(5.08,0)
  silkscreen extent -8.81,2 8.81,8, body extent -6.25,-0.89 6.25,8.01
XH-2.54-6P-LI [mm] "接插件2.54-6P"
  rect 1.8x3.9 smd: 0(-9.55,4.8) 0(9.55,4.8)
  rect 1.3x4.5 smd: 1(-6.35,0) 2(-3.81,0) 3(-1.27,0) 4(1.27,0) 5(3.81,0) 6(6.35,0)
  silkscreen extent -10,2 10,8, body extent -6.25,-0.89 6.25,8.01
XTAL-3225-2 [mm] "3225晶振两脚"
  rect 1.5x2.5 smd: 1(-1.2,0) 2(1.2,0)
  silkscreen extent -1.6,-1.5 1.6,1.5, body extent -1.6,-1.25 1.6,1.25, height 0.9

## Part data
C1 C5 C9 C11 C16 C17 C18 C19 C20 C21 C22 C23 C26 C27 C28 C29 C30 C31 C32 C34 C47 C52 C54 C58 C59 C63: library part CAP4, "贴片电容 20%"
C2 C3 C4 C60 C61 C62: library part CAP2, "电解电容"
C6 C8 C10 C12 C14 C41 C46 C51 C53 C55 C57 C64 C65 C66 C67 C68 C69 C70 C71: library part CAP4, "贴片电容 10%"
C7: library part CAP4, "贴片电容 5%"
C13 C15 C25 C33 C50 C56: library part CAP2, "钽电容"
C24: library part CAP4, "贴片电容"
C35 C48: library part CAP, "CBB电容"
C36 C38 C39 C40 C42 C43 C44 C45 C49: library part CAP, "贴片电容 5%"
C37: library part CAP, "贴片电容 20%"
D1 D2: library part DIODE2, "二极管 M7"
DS1 DS2 DS3 DS4 DS5: library part DISCHARE-1, "气体放电管 90V"
FB1 FB2 FB3 FB4: library part Inductor, "Inductor"
L1: library part CIZHU1, "磁珠电感 100R 100MHz"
LC1 LC2 LC3: library part SMD-EMIFIL-0603, "LC滤波器"
LED1: library part LED0, "LED"
P1 P8: library part SIP-6, "血压计接口"
P2: library part SIP-4
P3: library part SIP-5, "颈动脉传感器接口"
P4: library part SIP-5, "心音传感器接口"
P5: library part SIP-6, "心电接口"
P6 P7: library part SIP-2, "2.54mm- 2P立贴"
Q1 Q2: library part NPN-TO252, "NPN TO252"
Q3 Q4: library part NPN-1, "NPN"
Q5: library part MOSFET-P, "P-Channel MOSFET"
Q6: library part NPN, "NPN Bipolar Transistor"
R1 R2 R3 R4 R5 R6 R54 R55: library part R, "贴片电阻 1%"
R7 R8 R9 R10 R11 R12 R13 R14 R15 R16 R17 R18 R19 R21 R23: library part RES0, "贴片电阻 5%"
R20 R22 R24 R25 R35 R36 R37 R38 R39 R40 R41 R42 R43 R46 R47 R48 R50 R51 R52 R53: library part RES0, "贴片电阻 1%"
R26: library part RES2, "贴片电阻"
R27 R28 R29 R30: library part RES-SOP, "贴片电阻 5%"
R31 R32 R33 R34: library part RES2, "贴片电阻 5%"
R44 R45: library part RES0, "贴片电阻 1% 低温票电阻"
R49: library part RES4, "可调电阻"
R56 R57 R58 R59: library part Res1, "Resistor"
TP1 TP3: library part TP-1, "测试点"
TP2: library part TP_POINT, "测试点"
TP4 TP5 TP6 TP7 TP8 TP9: library part TP_POINT
TVS1 TVS2 TVS3 TVS4 TVS5 TVS6 TVS7 TVS8 TVS9: "单向TVS"
U1: library part ADS1293, "ECG AFE"
U2 U4 U9: library part MCP1802, "LDO"
U3: library part STM32F405RG, "MCU"
U5: library part MMR901, "压力传感器"
U6: library part LM358, "运放"
U7: library part LM358, "高精度运放"
U8: library part Component_1, "仪表运放"
VR1: library part LM1117, "三端稳压器"
Y1: library part XTAL, "晶振"

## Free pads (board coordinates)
  round 196.85 hole 137.8: 0(590.55,137.8) 0(590.55,2421.26) 0(4251.97,137.8) 0(4251.97,2421.26)

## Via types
v1: diameter 30, hole 20, Top Layer to Bottom Layer, tented both sides, 321 vias
v2: diameter 40, hole 25, Top Layer to Bottom Layer, tented both sides, 61 vias
v3: diameter 23.62, hole 11.81, Top Layer to Bottom Layer, tented both sides, 49 vias
v4: diameter 20, hole 12, Top Layer to Bottom Layer, tented both sides, 45 vias
v5: diameter 20, hole 12, Top Layer to Bottom Layer, 1 vias

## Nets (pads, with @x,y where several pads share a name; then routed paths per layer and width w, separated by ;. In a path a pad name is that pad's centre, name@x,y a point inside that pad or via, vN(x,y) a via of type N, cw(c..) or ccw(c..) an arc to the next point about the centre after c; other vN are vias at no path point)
ADS_ALA: R14.1 U3.38 | length 444.6
  Top Layer w10: U3.38@2907.48,879.92 3267.94,879.92 3323.02,935 R14.1@3329.25,935
ADS_CSB: R12.1 U3.37 | length 432.7
  Top Layer w10: U3.37@2907.48,860.24 3284.76,860.24 3310.35,885.83 3328.43,885.83 R12.1@3329.25,885
ADS_DRD: R7.1 U3.33 | length 461.7
  Top Layer w10: U3.33@2907.48,781.5 3167.76,781.5 3264.25,685 R7.1@3329.25,685
ADS_SCLK: R10.1 U3.34 | length 563.3
  Top Layer w10: U3.34@2907.48,801.18 3183.07,801.18 v3(3259.25,725) ; v3(3259.25,835) R10.1@3329.25,835
  Bottom Layer w10: v3(3259.25,725) v3(3259.25,835)
ADS_SDI: R9.1 U3.36 | length 444.8
  Top Layer w10: U3.36@2907.48,840.55 3209.25,840.55 3264.8,785 R9.1@3329.25,785
ADS_SDO: R8.1 U3.35 | length 457.3
  Top Layer w10: U3.35@2907.48,820.87 3198.82,820.87 3284.69,735 R8.1@3329.25,735
AV3.3: C37.2 C38.2 C46.2 C47.2 C51.2 C52.2 C53.2 C54.2 C55.2 C56.1 R44.1 R49.3 TP8.1 U5.1 U6.8 U7.8 U8.7 U9.5 | length 1005.2
  Top Layer w19.68: U5.1@2166.25,2440.23 v3(2263.69,2440.23) 2303.37,2440.23 ; v2@2208.27,1905 2234.72,1931.45 TP8.1@2234.72,1998.13 ; C47.2@2303.37,2412.43 2303.37,2440.23 ; C46.2@2303.37,2467.43 C46.2@2303.37,2465.39 2303.37,2440.23 ; C53.2@2589.25,1510 C52.2@2639.25,1510 U7.8@2639.25,1595 v3(2639.25,1660) ; U8.7@3450.35,1729.53 v3(3515.71,1729.53) 3517.24,1731.06 C37.2@3517.24,1880 ; U6.8@4025.35,1779.53 C54.2@4135.35,1779.53 C55.2@4135.35,1829.53 v3(4135.35,1868.58) ; C51.2@4195.35,1529.53 R44.1@4195.35,1579.53 v3@4238.78,1579.53
  other v1: 3789.81,1565 3843.95,1564.53
  other v2: 2202.16,1902.92
  other v3: 4239.25,1580
BP_POWER_EN: R58.2 R59.1 U3.26 | length 1422.5
  Top Layer w10: R59.1@1663.14,253.94 1663.14,282.92 1677.89,297.67 1743.85,297.67 R58.2@1745.19,299.01 v4(1745.19,351.74) v4@1745.65,352.2 ; v5(2718.36,638.68) 2718.43,638.75 2718.43,710.56 U3.26@2718.5,710.63
  Bottom Layer w10: v4(1745.19,351.74) 2385.62,351.74 2471.68,437.8 2471.68,589.57 2498.33,616.22 2699.52,616.22 v5@2718.36,635.07
ECG_CLK: R18.1 U3.41 | length 719.8
  Top Layer w10: U3.41@2907.48,938.98 2972.63,938.98 2981.95,929.66 v3(3211.34,929.66)
  Top Layer w11.81: v3(3229.25,625) R18.1@3329.25,625
  Bottom Layer w11.81: v3(3211.34,929.66) 3211.34,642.91 v3(3229.25,625)
EGND: C1.1 C2.2 C3.2 C4.2 C5.1 C6.1 C8.1 C9.1 C10.1 C11.1 C12.1 C13.2 C14.1 C15.2 C18.1 C19.1 C20.1 C21.1 C22.1 C23.2 C24.1 C25.2 C26.1 C27.1 C28.1 C29.1 C30.1 C31.1 C32.1 C33.2 C34.1 C37.1 C38.1 C39.2 C42.1 C43.2 C44.1 C45.1 C46.1 C47.1 C49.1 C50.2 C51.1 C52.1 C53.1 C54.1 C55.1 C56.2 C57.1 C58.1 C59.1 C60.2 C61.2 C62.2 C63.1 C64.1 C65.1 C66.2 C67.1 C68.1 C69.1 C70.1 C71.1 DS1.2 DS2.2 DS3.2 DS4.2 DS5.2 L2.3 LC1.2 LC2.2 LC3.2 P1.0 P1.4 P1.5 P3.0 P3.1 P3.4 P4.0 P4.1 P4.4 P5.0 P5.6 P6.0 P7.0 P8.0 P8.5 P8.6 Q1.3 Q2.3 Q6.2 R5.1 R6.1 R19.1 R24.2 R29.2 R30.2 R32.2 R36.2 R42.1 R45.1 R46.2 R49.1 R59.2 SWD1.4 TP3.1 TVS1.1 TVS2.1 TVS3.1 TVS4.1 TVS5.1 TVS6.1 TVS7.1 TVS8.1 TVS9.1 U1.0 U1.14 U1.27 U2.2 U3.12 U3.18 U3.63 U4.2 U5.3 U5.8 U5.12 U6.4 U7.4 U8.4 U9.2 VR1.1 | length 1634.6
  Top Layer w10: U3.12@2470.47,860.24 2571.56,860.24 ; v4(2546.33,1216.73) 2561.02,1202.04 U3.63@2561.02,1147.64 2561.02,1081.1 v1(2617.13,1025) ; U3.18@2561.02,710.63 2561.02,849.7 2571.56,860.24 ; v1(2621.36,910.04) 2571.56,860.24 ; U1.14@3550.2,850.39 3550.2,809.06 U1.0@3609.25,750 3648.62,710.63 U1.27@3648.62,649.61 ; C11.1@3734.25,470 C12.1@3784.25,470 ; TVS2.1@3987.8,2060 TVS2.1@3987.8,2073.62 ; 4054.25,2102.19 C59.1@4054.25,2140.07 ; C71.1@4620,465 4620,444.95 v4(4645.62,419.34) ; C70.1@4620,595 v4(4650.75,595) ; C69.1@4620,720 v4(4650.75,720) ; C68.1@4620,850 v4(4650.75,850) ; C67.1@4620,1040 v4(4620,1118.34)
  Top Layer w19.68: C53.1@2589.25,1450 C52.1@2626.03,1450 ; v4(3035.26,1078.89) 3064.25,1107.88 C21.1@3064.25,1150 C18.1@3064.25,1200 C19.1@3064.25,1250 R32.2@3064.25,1300 ; v4(3906.95,460) TVS6.1@3937.8,460 ; v4(3906.95,635) TVS7.1@3937.8,635 ; v4(3906.95,801.18) TVS8.1@3937.8,801.18 ; v4(3906.95,948.82) TVS9.1@3937.8,948.82 ; LC3.2@3915.35,1374.53 U9.2@3915.35,1449.41 ; R45.1@4195.35,1629.53 C49.1@4195.35,1679.53
  other v1: 1946.77,50.85 3183.94,53.09 4496.39,53.09 3690.15,54.47 1524.22,62.89 4757.31,77.94 2122.32,93.46 3488.59,102.79 1926.89,107.66 3922.58,108.37 3824.21,108.95 2414.06,117.89 3738.73,117.89 2534.25,120 3249.26,140.14 4488.11,152.49 4598.55,153.87 1505.26,156.41 3736.07,166.31 2099.17,167.56 3114.01,168.23 4035.29,169.05 3922.58,181.12 4737.99,181.48 4847.05,187 2534.25,205.64 2411.5,211.77 4601.31,239.46 4471.54,243.6 3114.01,245 3488.59,245 3609.25,244.99 4761.46,246.36 3029.22,259.14 3054.49,264.03 2103.21,265.02 4108.02,279.14 4681.46,287.01 1612.36,299.73 2249.04,303.42 4422.34,303.22 1875.62,312.94 3183.94,333.97 3114.01,336.28 4532.28,343 4617.77,362.02 3104.25,375 1528.51,379.2 1887.16,380.41 4512.74,385.45 4708.16,390.22 4819.12,390.22 4761.46,403.1 3129.67,414.8 3494.8,415.48 3574.25,415.48 3169.69,419.09 3679.49,420.44 3734.25,420.44 3789.81,427.29 2258.65,443.16 1931.6,451.03 4091.05,460 4933.26,460.96 1371.72,465.38 1668.31,465.38 1975.29,476.39 3183.94,480.76 3129.67,485.73 4382.25,485.73 2897.54,499.44 3870.35,506.89 3091.88,511.92 2643.26,525.97 4963.98,525.97 1026.07,538.27 3183.94,550 2099.03,592.06 3475.31,605.23 3699.25,605 4963.98,605.23 2760.36,640.14 1010.61,649.8 4087.34,649.61 4963.98,675.98 2100.02,715.03 3579.25,730.32 3648.62,730.32 2420.77,734.99 2912.18,737.43 4963.98,745 3579.25,785 3648.62,785 4087.34,801.18 2621.36,814.2 2761.93,818.42 4963.98,818.42 2110.46,823.39 1856.91,827.51 2222.88,830.42 2694.25,835 464.7,859.18 176.59,862.74 357.96,867.36 3772.34,867.36 640.77,884.08 2392.83,883.57 4963.98,885 2279.42,892.82 2062.65,902.99 2757.87,910.04 558.96,914.32 256.17,938.98 1824.76,946.74 2088.79,954.65 4086.63,958.66 4963.98,958.66 2686.76,966.9 420.24,971.23 112.41,975 2319.69,991.21 3400.63,996.63 1924.26,1000 2754.25,1025 4959.6,1025.45 3450.35,1028.7 2086.86,1047.39 2344.47,1061.56 169.48,1063.71 403.06,1067.83 1824.76,1067.83 537.2,1071.51 636.42,1073.35 3652.91,1082.99 4492.83,1087.5 3778.54,1094.04 103.46,1101.35 3512.07,1108.92 4406.04,1136.4 3596.01,1153.07 3716.7,1155.9 3854.25,1155.9 2008.86,1169.1 3968.47,1169.1 4091.05,1171.93 4583.9,1171.93 4675.66,1173.36 4761.46,1173.36 3185.97,1175.03 4901.25,1181.37 3389.25,1216.73 2189.25,1220 2091.73,1231.48 91.62,1272.09 2091.73,1319.15 439.81,1325.08 583.14,1332.43 4135.35,1332.43 722.79,1337.95 1422.8,1356.84 4708.16,1359.45 1304.82,1365.62 1174.3,1381.94 4187.8,1381.94 4413.71,1381.94 2991.01,1395.28 2875.4,1397.5 4518.76,1399.39 728.3,1413.29 425.11,1416.96 577.62,1416.96 1452.85,1433.38 91.62,1443.57 1546.11,1443.57 1342.47,1462.26 3035.26,1462.26 2925.88,1470.64 1629.88,1476.07 4469.7,1479.25 1267.17,1483.6 1924.25,1483.6 4381.84,1495.23 1176.65,1501.49 4570.1,1502.07 2397.73,1505.33 3915.36,1504.52 1436.6,1511.21 1741.58,1517.48 1658.74,1529.53 1558.34,1532.54 1358.79,1540.07 91.62,1577.8 1272.2,1580.5 2243.5,1666.88 1066.4,1676.05 4390.97,1717.71 2589.25,1729.53 1562.47,1736.21 1412.41,1758.88 3556.94,1762.21 828.5,1770.16 1064.56,1779.53 1465.61,1783.92 488.17,1784.95 2172.18,1790.03 1803.22,1798.19 66.1,1825.29 949.83,1838.22 2415.57,1847.76 1408.05,1877.31 452.66,1879.65 1064.56,1883.69 1184,1887.36 4187.8,1887.36 4389.11,1887.36 2130.44,1905 2001.31,1908.53 141.72,1910.36 3778.54,1918.52 4108.02,1918.52 2420.77,1933.23 3456.53,1939.06 3579.25,1939.06 695.33,1956.6 3129.67,1956.6 1356.78,1958.99 1793.6,1958.76 897.07,1963.2 590.55,1965 2986.78,1969.13 3187.96,1983.39 2836.29,1990 2128.93,1998.13 207.04,2003.94 500.01,2006.9 327.61,2008.03 4331.64,2017.78 2740.68,2048.28 667.89,2052.14 2014.25,2060 2597.77,2072.36 3736.07,2086.24 1783.7,2092.52 2137.36,2092.52 2234.72,2094.8 4497.08,2109.06 565.12,2122.32 932.08,2125.28 153.77,2134.16 2458.56,2137.3 357.96,2140.07 1741.58,2140.07 1301.49,2169.71 2491.42,2174.64 4264.95,2176.21 1482.41,2188.81 3262.29,2198.72 3379.37,2201.09 4378.08,2212.37 4637.42,2215.16 1774.66,2218.27 2434.67,2225.41 2043.14,2237.04 348.59,2250 4562.11,2263.08 900.87,2268.98 1499.25,2270 160.62,2288.44 4710.24,2291.59 791.99,2329.05 2046.68,2349.68 2101.38,2376.28 1639.65,2425.95 1158.29,2453.87 755.85,2465.39
  other v2: 3382.98,60.34 2735.85,90.37 2867.02,175.71 1649.85,391.47 1099.72,795.12 2949.02,1145.15 1262.24,1259 1115.27,1262.95 1531.37,1349.38 4847.05,1350 3564.25,1387.8 2825.88,1470.64 2324.85,1615 3344.32,1654.06 3922.58,1660 2234.72,1750.68 3334.78,1750.68 908.54,1761.48 289.56,1767.29 159.27,1768.22 652.51,1837.09 2234.72,1847.76 1838.37,1887.36 2571.56,1935.13 2912.18,1979.19 2439.36,1987.86 2511.81,2008.03 3527.52,2060.21 2426.33,2069.76 2508.23,2086.51 4367.15,2126.5
  other v4: 4195.35,1654.53
EVDD: C9.2 C10.2 C11.2 C12.2 C14.2 C15.1 FB2.2 R21.1 R23.1 TP4.1 U1.22 U1.28 | length 1158
  Top Layer w10: TP4.1@3259.25,544.68 3411.34,544.68 3426.02,530 C9.2@3534.25,530 ; U1.22@3550.2,649.61 v3(3550.2,605) 3550.2,530.94 3549.25,530 C10.2@3584.25,530 ; U1.28@3668.31,649.61 3669.01,648.9 v1(3768.94,648.9) ; C11.2@3734.25,530 3734.25,614.21 v1(3768.94,648.9) ; C12.2@3784.25,530 3784.25,635 3769.65,649.61 v1(3768.94,648.9)
  Top Layer w15.75: R21.1@3539.25,1005 v3(3539.25,1055.24)
  Top Layer w20: v4@3634.25,439.26 R23.1@3634.25,470
  Bottom Layer w10: v1(3819.25,345) 3907.04,345 3970.5,281.54 3970.5,178.98
  other v1: 3762.89,344.37 3709.65,345 3824.21,394.55
  other v4: 3634.33,437.56
GND_IN: L2.4 P2.1 P2.2 pad.0@590.55,137.8
  other v1: 860.87,49.64 757.04,50.78 121.54,80.44 245.9,80.44 352.01,82.73 428.45,88.43 884.83,137.49 775.23,140.14 115.83,187 348.59,194.54 256.17,199.1 795.84,217.36 430.73,229.91 711.41,259.57 112.41,301.32 374.83,305.21 243.62,310.92 494.63,317.76 625.84,318.9 115.83,409.04 249.32,427.29 482.08,437.56 374.83,443.16 120.4,509.44 244.76,524.27 390.8,544.81 467.24,604.14 112.41,641.79 403.35,705.68
MMR_CS: U3.55 U5.5 | length 1777.9
  Top Layer w10: U5.5@1961.33,2352.43 1918.37,2352.43 1893.37,2327.43 1893.37,1800.88 2362.13,1332.13 2665.91,1332.13 2718.78,1279.25 U3.55@2718.78,1147.64
MMR_DIN: U3.53 U5.4 | length 2068.5
  Top Layer w10: v3(1838.37,2022.43) 1838.37,2406.45 1872.15,2440.23 U5.4@2016.25,2440.23 ; v4(1935.12,2022.34) 1935.12,1823.03 2390.28,1367.87 2414.61,1367.87 ; 2414.61,1369.25 2695.71,1369.25 2757.87,1307.09 U3.53@2757.87,1147.64
  Bottom Layer w10: v3(1838.37,2022.43) 1935.03,2022.43 v4(1935.12,2022.34)
MMR_DO: U3.52 U5.7 | length 1627
  Top Layer w10: U5.7@1961.33,2252.43 1961.33,1830.05 2404.25,1387.13 2718.48,1387.13 2777.56,1328.05 U3.52@2777.56,1147.64
MMR_RD: U3.54 U5.6 | length 1716.5
  Top Layer w10: U5.6@1961.33,2302.43 1923.37,2302.43 1912.24,2291.3 1912.24,1812.01 2374.25,1350 2676.34,1350 2738.46,1287.87 U3.54@2738.46,1147.64
MMR_SCLK: U3.51 U5.9 | length 1509.8
  Top Layer w10: U5.9@2066.25,2172.51 2066.25,1764.92 2424.25,1406.92 2424.25,1405 2735.17,1405 2797.24,1342.93 U3.51@2797.24,1147.64
MOTOR: C17.2 R28.2 U3.61 | length 1217.9
  Top Layer w10: C17.2@1721.11,1620.73 1721.5,1620.73 R28.2@1721.5,1670.73 1982.27,1670.73 2340.01,1312.99 2557.68,1312.99 2600.67,1270 U3.61@2600.67,1147.64
NetC1_2: C1.2 C2.1 FB4.2 TP1.1 VR1.3 | length 345.9
  Top Layer w10: FB4.2@1066.4,944.06 TP1.1@1066.4,1091.29
  Top Layer w40: C2.1@1209.25,743.11 C1.2@1209.25,850.39 VR1.3@1209.25,941.78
